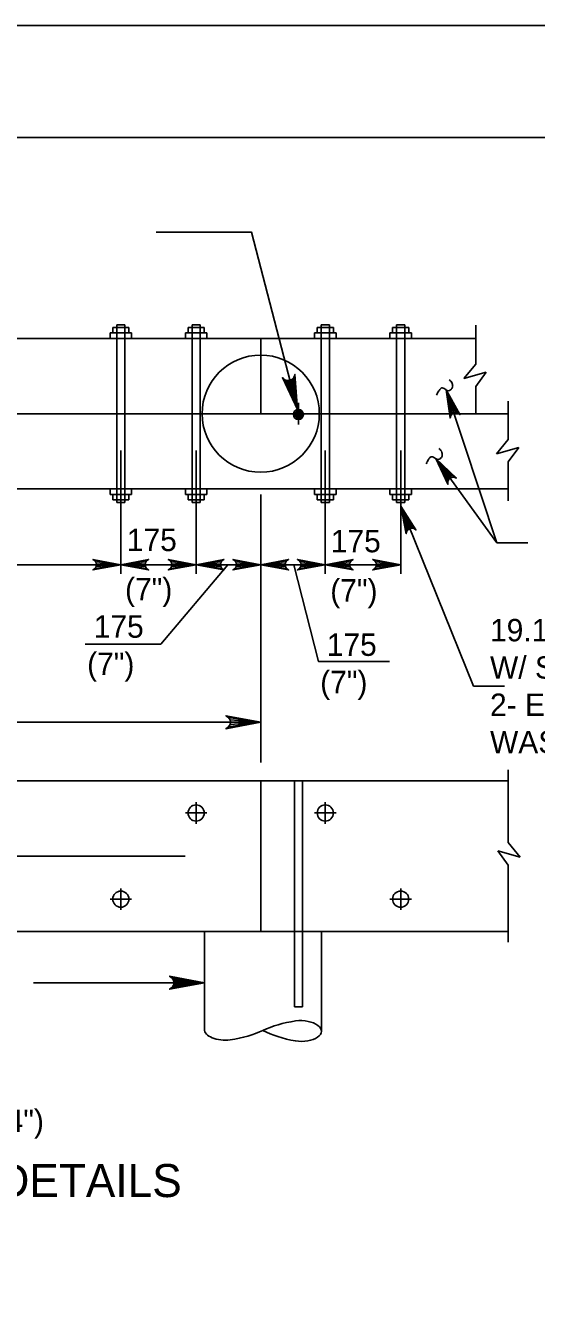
# Model space of a CAD drawing. Extents: x 635440 to 640306, y 296653 to 298484.
# Drawn here: x 639129.9 to 639198.4, y 298265 to 298435.5 of the extents above; entities that cross this region are included whole.
import ezdxf

# ---------------------------------------------------------------- set-up
doc = ezdxf.new("R2010")
doc.units = 0
for name, color, linetype in [('2', 7, 'Continuous'), ('4', 7, 'Continuous'), ('5', 7, 'Continuous'), ('52', 7, 'Continuous'), ('PLT-BNDY', 7, 'Continuous')]:
    doc.layers.add(name, color=color, linetype=linetype)

msp = doc.modelspace()

# ---------------------------------------------------------------- linework, layer by layer
at = {"layer": '2'}
msp.add_line((638475.46, 298420.46), (639261.46, 298420.46), dxfattribs=at)
at = {"layer": '4'}
for p, q in [((639142.14, 298395.34), (639143.22, 298395.34)), ((639142.14, 298395.34), (639142.14, 298371.55)), ((639143.22, 298395.34), (639143.22, 298371.55)), ((639152.23, 298395.34), (639153.31, 298395.34)), ((639152.23, 298395.34), (639152.23, 298371.55)), ((639153.31, 298395.34), (639153.31, 298371.55)), ((639169.53, 298395.34), (639170.62, 298395.34)), ((639169.53, 298395.34), (639169.53, 298371.55)), ((639170.62, 298395.34), (639170.62, 298371.55)), ((639179.63, 298395.34), (639180.71, 298395.34)), ((639179.63, 298395.34), (639179.63, 298371.55)), ((639180.71, 298395.34), (639180.71, 298371.55)), ((639190.23, 298390.09), (639190.23, 298395.3)), ((639190.23, 298393.53), (639034.58, 298393.53)), ((639141.24, 298394.25), (639144.12, 298394.25)), ((639141.24, 298393.53), (639141.24, 298394.25)), ((639141.6, 298394.98), (639143.76, 298394.98)), ((639141.6, 298394.25), (639141.6, 298394.98)), ((639143.76, 298394.25), (639143.76, 298394.98)), ((639144.12, 298393.53), (639144.12, 298394.25)), ((639151.33, 298393.53), (639151.33, 298394.25)), ((639151.33, 298394.25), (639154.22, 298394.25)), ((639151.69, 298394.25), (639151.69, 298394.98)), ((639151.69, 298394.98), (639153.85, 298394.98)), ((639153.85, 298394.25), (639153.85, 298394.98)), ((639154.22, 298393.53), (639154.22, 298394.25)), ((639161.42, 298393.53), (639161.42, 298383.44)), ((639168.63, 298393.53), (639168.63, 298394.25)), ((639168.63, 298394.25), (639171.52, 298394.25)), ((639168.99, 298394.25), (639168.99, 298394.98)), ((639168.99, 298394.98), (639171.16, 298394.98)), ((639171.16, 298394.25), (639171.16, 298394.98)), ((639171.52, 298393.53), (639171.52, 298394.25)), ((639178.72, 298393.53), (639178.72, 298394.25)), ((639178.72, 298394.25), (639181.61, 298394.25)), ((639179.09, 298394.25), (639179.09, 298394.98)), ((639179.09, 298394.98), (639181.25, 298394.98)), ((639181.25, 298394.25), (639181.25, 298394.98)), ((639181.61, 298393.53), (639181.61, 298394.25)), ((639190.23, 298390.09), (639188.64, 298388.14)), ((639188.64, 298388.14), (639191.62, 298388.98)), ((639191.62, 298388.98), (639190.23, 298387.07)), ((639190.23, 298383.44), (639190.23, 298387.07)), ((639194.59, 298380), (639194.59, 298385.12)), ((639194.59, 298383.44), (639030.22, 298383.44)), ((639167.91, 298383.44), (639165.03, 298383.44)), ((639166.47, 298384.88), (639166.47, 298382)), ((639194.59, 298380), (639193, 298378.05)), ((639193, 298378.05), (639195.98, 298378.89)), ((639195.98, 298378.89), (639194.59, 298376.98)), ((639194.59, 298371.77), (639194.59, 298376.98)), ((639194.59, 298373.35), (639030.22, 298373.35)), ((639141.24, 298373.35), (639141.24, 298372.63)), ((639144.12, 298373.35), (639144.12, 298372.63)), ((639151.33, 298373.35), (639151.33, 298372.63)), ((639154.22, 298373.35), (639154.22, 298372.63)), ((639168.63, 298373.35), (639168.63, 298372.63)), ((639171.52, 298373.35), (639171.52, 298372.63)), ((639178.72, 298373.35), (639178.72, 298372.63)), ((639181.61, 298373.35), (639181.61, 298372.63)), ((639141.24, 298372.63), (639144.12, 298372.63)), ((639141.6, 298372.63), (639141.6, 298371.91)), ((639141.6, 298371.91), (639143.76, 298371.91)), ((639142.14, 298371.55), (639143.22, 298371.55)), ((639143.76, 298372.63), (639143.76, 298371.91)), ((639151.33, 298372.63), (639154.22, 298372.63)), ((639151.69, 298372.63), (639151.69, 298371.91)), ((639151.69, 298371.91), (639153.85, 298371.91)), ((639152.23, 298371.55), (639153.31, 298371.55)), ((639153.85, 298372.63), (639153.85, 298371.91)), ((639168.63, 298372.63), (639171.52, 298372.63)), ((639168.99, 298372.63), (639168.99, 298371.91)), ((639168.99, 298371.91), (639171.16, 298371.91)), ((639169.53, 298371.55), (639170.62, 298371.55)), ((639171.16, 298372.63), (639171.16, 298371.91)), ((639178.72, 298372.63), (639181.61, 298372.63)), ((639179.09, 298372.63), (639179.09, 298371.91)), ((639179.09, 298371.91), (639181.25, 298371.91)), ((639179.63, 298371.55), (639180.71, 298371.55)), ((639181.25, 298372.63), (639181.25, 298371.91)), ((639194.59, 298335.7), (639194.59, 298325.98)), ((639194.59, 298334.26), (639030.22, 298334.26)), ((639161.42, 298334.26), (639161.42, 298314.08)), ((639165.93, 298334.26), (639165.93, 298303.98)), ((639167.01, 298334.26), (639167.01, 298303.98)), ((639152.77, 298331.38), (639152.77, 298328.5)), ((639170.07, 298331.38), (639170.07, 298328.5)), ((639154.22, 298329.94), (639151.33, 298329.94)), ((639171.52, 298329.94), (639168.63, 298329.94)), ((639194.59, 298325.98), (639196.17, 298324.03)), ((639193.19, 298324.88), (639194.59, 298322.96)), ((639196.17, 298324.03), (639193.19, 298324.88)), ((639194.59, 298322.96), (639194.59, 298312.63)), ((639142.68, 298319.84), (639142.68, 298316.96)), ((639180.17, 298319.84), (639180.17, 298316.96)), ((639144.12, 298318.4), (639141.24, 298318.4)), ((639181.61, 298318.4), (639178.72, 298318.4)), ((639194.59, 298314.08), (639030.22, 298314.08)), ((639153.88, 298314.08), (639153.88, 298300.94)), ((639169.56, 298314.08), (639169.56, 298300.68)), ((639165.93, 298303.98), (639167.01, 298303.98))]:
    msp.add_line(p, q, dxfattribs=at)
for centre, radius in [((639161.42, 298383.44), 7.85), ((639152.77, 298329.94), 1.08), ((639170.07, 298329.94), 1.08), ((639142.68, 298318.4), 1.08), ((639180.17, 298318.4), 1.08)]:
    msp.add_circle(centre, radius, dxfattribs=at)
for centre, major_axis, start_param, end_param in [((639169.5, 298296.76), (11.09, -0.18), 1.89032, 2.356194), ((639166.78, 298300.73), (2.78, -0.05), 4.455588, 8.110783), ((639156.65, 298300.89), (-2.78, 0.05), 0, 1.827597), ((639153.94, 298304.86), (-11.09, 0.18), 1.89032, 2.356194), ((639169.63, 298304.6), (11.09, -0.18), 3.926991, 4.392865)]:
    msp.add_ellipse(centre, major_axis=major_axis, ratio=0.5, start_param=start_param, end_param=end_param, dxfattribs=at)
at = {"layer": '5'}
for p, q in [((639186.27, 298386.63), (639193.05, 298366.13)), ((639142.68, 298378.51), (639142.68, 298361.97)), ((639152.77, 298378.51), (639152.77, 298361.97)), ((639170.07, 298378.51), (639170.07, 298361.97)), ((639180.17, 298378.51), (639180.17, 298361.97)), ((639184.89, 298377.42), (639193.05, 298366.13)), ((639161.42, 298372.63), (639161.42, 298336.71)), ((639193.05, 298366.13), (639197.22, 298366.13)), ((639112.4, 298363.21), (639180.17, 298363.21)), ((639189.93, 298346.95), (639194.09, 298346.95)), ((639161.42, 298342.1), (639052.08, 298342.1)), ((639151.3, 298324.17), (639073.07, 298324.17))]:
    msp.add_line(p, q, dxfattribs=at)
for points in [[(639166.33, 298383.98), (639160.18, 298407.78), (639147.4, 298407.78)], [(639166.33, 298383.98), (639164.32, 298388.27), (639164.48, 298388.13), (639164.65, 298387.99), (639164.82, 298387.94), (639165, 298387.89), (639165.15, 298387.9), (639165.31, 298387.91), (639165.46, 298387.98), (639165.6, 298388.04), (639165.73, 298388.17), (639165.86, 298388.3), (639165.93, 298388.51), (639166.01, 298388.71), (639166.33, 298383.98), (639165.93, 298388.51), (639165.86, 298388.3), (639166.33, 298383.98), (639165.73, 298388.17), (639165.6, 298388.04), (639166.33, 298383.98), (639165.46, 298387.98), (639165.31, 298387.91), (639166.33, 298383.98), (639165.15, 298387.9), (639165, 298387.89), (639166.33, 298383.98), (639164.82, 298387.94), (639164.65, 298387.99), (639166.33, 298383.98), (639164.48, 298388.13)], [(639186.27, 298386.63), (639188.11, 298383.31), (639187.83, 298383.52), (639187.55, 298383.58), (639187.3, 298383.55), (639187.07, 298383.43), (639186.88, 298383.21), (639186.78, 298382.87), (639186.27, 298386.63), (639186.88, 298383.21), (639187.07, 298383.43), (639186.27, 298386.63), (639187.3, 298383.55), (639187.55, 298383.58), (639186.27, 298386.63), (639187.83, 298383.52)], [(639184.89, 298377.42), (639187.64, 298374.81), (639187.31, 298374.93), (639187.02, 298374.9), (639186.79, 298374.79), (639186.61, 298374.61), (639186.5, 298374.34), (639186.5, 298373.99), (639184.89, 298377.42), (639186.5, 298374.34), (639186.61, 298374.61), (639184.89, 298377.42), (639186.79, 298374.79), (639187.02, 298374.9), (639184.89, 298377.42), (639187.31, 298374.93)], [(639180.17, 298371.07), (639189.93, 298346.95)], [(639180.17, 298371.07), (639182.21, 298367.87), (639181.92, 298368.06), (639181.63, 298368.11), (639181.39, 298368.05), (639181.17, 298367.92), (639180.99, 298367.69), (639180.92, 298367.35), (639180.17, 298371.07), (639180.99, 298367.69), (639181.17, 298367.92), (639180.17, 298371.07), (639181.39, 298368.05), (639181.63, 298368.11), (639180.17, 298371.07), (639181.92, 298368.06)], [(639142.68, 298363.21), (639138.95, 298362.51), (639139.24, 298362.71), (639139.39, 298362.96), (639139.43, 298363.21), (639139.39, 298363.46), (639139.24, 298363.71), (639138.95, 298363.91), (639142.68, 298363.21), (639139.24, 298363.71), (639139.39, 298363.46), (639142.68, 298363.21), (639139.43, 298363.21), (639139.39, 298362.96), (639142.68, 298363.21), (639139.24, 298362.71)], [(639142.68, 298363.21), (639146.41, 298362.51), (639146.12, 298362.71), (639145.97, 298362.96), (639145.93, 298363.21), (639145.97, 298363.46), (639146.12, 298363.71), (639146.41, 298363.91), (639142.68, 298363.21), (639146.12, 298363.71), (639145.97, 298363.46), (639142.68, 298363.21), (639145.93, 298363.21), (639145.97, 298362.96), (639142.68, 298363.21), (639146.12, 298362.71)], [(639152.77, 298363.21), (639149.04, 298362.51), (639149.33, 298362.71), (639149.48, 298362.96), (639149.52, 298363.21), (639149.48, 298363.46), (639149.33, 298363.71), (639149.04, 298363.91), (639152.77, 298363.21), (639149.33, 298363.71), (639149.48, 298363.46), (639152.77, 298363.21), (639149.52, 298363.21), (639149.48, 298362.96), (639152.77, 298363.21), (639149.33, 298362.71)], [(639152.77, 298363.21), (639156.5, 298362.51), (639156.21, 298362.71), (639156.07, 298362.96), (639156.02, 298363.21), (639156.07, 298363.46), (639156.21, 298363.71), (639156.5, 298363.91), (639152.77, 298363.21), (639156.21, 298363.71), (639156.07, 298363.46), (639152.77, 298363.21), (639156.02, 298363.21), (639156.07, 298362.96), (639152.77, 298363.21), (639156.21, 298362.71)], [(639161.42, 298363.21), (639157.69, 298362.51), (639157.98, 298362.71), (639158.13, 298362.96), (639158.17, 298363.21), (639158.13, 298363.46), (639157.98, 298363.71), (639157.69, 298363.91), (639161.42, 298363.21), (639157.98, 298363.71), (639158.13, 298363.46), (639161.42, 298363.21), (639158.17, 298363.21), (639158.13, 298362.96), (639161.42, 298363.21), (639157.98, 298362.71)], [(639161.42, 298363.21), (639165.15, 298362.51), (639164.87, 298362.71), (639164.72, 298362.96), (639164.67, 298363.21), (639164.72, 298363.46), (639164.87, 298363.71), (639165.15, 298363.91), (639161.42, 298363.21), (639164.87, 298363.71), (639164.72, 298363.46), (639161.42, 298363.21), (639164.67, 298363.21), (639164.72, 298362.96), (639161.42, 298363.21), (639164.87, 298362.71)], [(639170.07, 298363.21), (639166.34, 298362.51), (639166.63, 298362.71), (639166.78, 298362.96), (639166.82, 298363.21), (639166.78, 298363.46), (639166.63, 298363.71), (639166.34, 298363.91), (639170.07, 298363.21), (639166.63, 298363.71), (639166.78, 298363.46), (639170.07, 298363.21), (639166.82, 298363.21), (639166.78, 298362.96), (639170.07, 298363.21), (639166.63, 298362.71)], [(639170.07, 298363.21), (639173.8, 298362.51), (639173.52, 298362.71), (639173.37, 298362.96), (639173.32, 298363.21), (639173.37, 298363.46), (639173.52, 298363.71), (639173.8, 298363.91), (639170.07, 298363.21), (639173.52, 298363.71), (639173.37, 298363.46), (639170.07, 298363.21), (639173.32, 298363.21), (639173.37, 298362.96), (639170.07, 298363.21), (639173.52, 298362.71)], [(639180.17, 298363.21), (639176.44, 298362.51), (639176.72, 298362.71), (639176.87, 298362.96), (639176.92, 298363.21), (639176.87, 298363.46), (639176.72, 298363.71), (639176.44, 298363.91), (639180.17, 298363.21), (639176.72, 298363.71), (639176.87, 298363.46), (639180.17, 298363.21), (639176.92, 298363.21), (639176.87, 298362.96), (639180.17, 298363.21), (639176.72, 298362.71)], [(639161.42, 298342.1), (639156.76, 298341.22), (639157.12, 298341.47), (639157.31, 298341.78), (639157.36, 298342.1), (639157.31, 298342.41), (639157.12, 298342.72), (639156.76, 298342.97), (639161.42, 298342.1), (639157.12, 298342.72), (639157.31, 298342.41), (639161.42, 298342.1), (639157.36, 298342.1), (639157.31, 298341.78), (639161.42, 298342.1), (639157.12, 298341.47)], [(639153.88, 298307.2), (639130.99, 298307.2)], [(639153.88, 298307.2), (639149.22, 298308.07), (639149.39, 298307.95), (639149.57, 298307.83), (639149.67, 298307.67), (639149.76, 298307.51), (639149.79, 298307.36), (639149.81, 298307.2), (639149.79, 298307.04), (639149.76, 298306.89), (639149.67, 298306.73), (639149.57, 298306.58), (639149.39, 298306.45), (639149.22, 298306.33), (639153.88, 298307.2), (639149.39, 298306.45), (639149.57, 298306.58), (639153.88, 298307.2), (639149.67, 298306.73), (639149.76, 298306.89), (639153.88, 298307.2), (639149.79, 298307.04), (639149.81, 298307.2), (639153.88, 298307.2), (639149.79, 298307.36), (639149.76, 298307.51), (639153.88, 298307.2), (639149.67, 298307.67), (639149.57, 298307.83), (639153.88, 298307.2), (639149.39, 298307.95)]]:
    msp.add_lwpolyline(points, dxfattribs=at)
for points in [[(639180.17, 298371.07), (639181.05, 298368.24), (639181.5, 298368.42)], [(639158.54, 298342.58), (639158.54, 298341.61), (639161.42, 298342.1)]]:
    msp.add_lwpolyline(points, close=True, dxfattribs=at)
for radius in [0.667, 0.5, 0.333, 0.167]:
    msp.add_circle((639166.47, 298383.33), radius, dxfattribs=at)
for centre, radius, start, end in [((639188.56, 298384.16), 4.02, 138.3715, 144.4201), ((639185.67, 298386.74), 0.151, 106.7241, 138.3715), ((639185.67, 298386.71), 0.18, 77.4691, 106.7241), ((639185.3, 298385.01), 1.92, 68.5955, 77.4691), ((639185.73, 298386.12), 0.729, 48.0647, 68.5955), ((639186.59, 298387.07), 0.556, 228.0647, 251.6054), ((639186.17, 298387.08), 1.01, 39.8006, 60.652), ((639186.53, 298387.09), 0.568, 287.1056, 318.9992), ((639186.43, 298387.3), 0.677, 14.2351, 39.8006), ((639186.34, 298387.25), 0.816, 318.9992, 333.439), ((639186.56, 298387.14), 0.571, 333.439, 350.7201), ((639185.33, 298387.02), 1.81, 5.7096, 14.2351), ((639186.55, 298387.14), 0.587, 350.7201, 5.7096), ((639187.15, 298385.22), 2.27, 153.439, 161.9608), ((639186.93, 298385.33), 2.02, 144.4201, 153.439), ((639186.56, 298386.98), 0.461, 251.6054, 287.1056), ((639184.78, 298377.88), 1.01, 39.8006, 60.652), ((639185.04, 298378.09), 0.677, 14.2351, 39.8006), ((639183.94, 298377.81), 1.81, 5.7096, 14.2351), ((639185.76, 298376.01), 2.27, 153.439, 161.9608), ((639185.55, 298376.12), 2.02, 144.4201, 153.439), ((639187.17, 298374.96), 4.02, 138.3715, 144.4201), ((639184.28, 298377.53), 0.151, 106.7241, 138.3715), ((639184.28, 298377.5), 0.18, 77.4691, 106.7241), ((639183.91, 298375.8), 1.92, 68.5955, 77.4691), ((639184.34, 298376.91), 0.729, 48.0647, 68.5955), ((639185.2, 298377.87), 0.556, 228.0647, 251.6054), ((639185.17, 298377.78), 0.461, 251.6054, 287.1056), ((639185.14, 298377.88), 0.568, 287.1056, 318.9992), ((639184.95, 298378.04), 0.816, 318.9992, 333.439), ((639185.17, 298377.93), 0.571, 333.439, 350.7201), ((639185.16, 298377.93), 0.587, 350.7201, 5.7096)]:
    msp.add_arc(centre, radius, start, end, dxfattribs=at)
at = {"layer": '52'}
for points in [[(639157.01, 298363.21), (639148.04, 298352.55), (639137.91, 298352.55)], [(639165.84, 298363.21), (639169.15, 298350.24), (639178.69, 298350.24)]]:
    msp.add_lwpolyline(points, dxfattribs=at)
at = {"layer": 'PLT-BNDY'}
msp.add_lwpolyline([(638435.46, 298435.46), (639276.46, 298435.46), (639276.46, 297841.46), (638435.46, 297841.46)], close=True, dxfattribs=at)

# ---------------------------------------------------------------- texts
at = {"layer": '5'}
for s, height, p in [('175', 3, (639143.49, 298365.03)), ('175', 3, (639170.81, 298364.87)), ('(7")', 3, (639143.25, 298358.43)), ('(7")', 3, (639170.74, 298358.27)), ('175', 3, (639139.05, 298353.42)), ('19.1 (3/4")  BOLT', 3.0001, (639192.14, 298352.94)), ('175', 3, (639170.27, 298350.99)), ('(7")', 3, (639138.17, 298348.42)), ('W/ STD. NUT AND', 3.0001, (639192.14, 298347.94)), ('(7")', 3, (639169.39, 298345.99)), ('2- ENLARGED', 3.0001, (639192.14, 298342.94)), ('WASHERS (TYP.)', 3.0001, (639192.14, 298337.94)), ('BEARING SILL: 2-225x350 (9"x14")', 3.0001, (639068.43, 298287.19)), ('BEARING SILL SPLICE DETAILS', 4.4294, (639061.3, 298278.48))]:
    msp.add_text(s, height=height, dxfattribs=at).set_placement(p)

doc.saveas('drawing.dxf')
